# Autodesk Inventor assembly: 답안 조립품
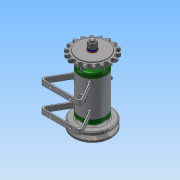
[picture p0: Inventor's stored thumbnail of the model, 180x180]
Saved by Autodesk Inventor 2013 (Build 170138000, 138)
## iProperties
Created: 2016-03
Part Number: 답안 조립품
Document SubType Name: Assembly
Designer: Administrator
Author: Administrator
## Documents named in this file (16)
- C:\Users\Administrator\Desktop\460308V1024\답안 조립품.iam
- C:\Users\Administrator\Desktop\460308V1024\본체.ipt
- C:\Users\Administrator\Desktop\460308V1024\V벨트풀리.ipt
- C:\Users\Administrator\Desktop\460308V1024\너트 M 8.ipt
- C:\Users\Administrator\Desktop\460308V1024\니플 M 6 x 0.75.ipt
- C:\Users\Administrator\Desktop\460308V1024\베어링 15 x 32 x 9.ipt
- C:\Users\Administrator\Desktop\460308V1024\볼트 M 6 x 8.ipt
- C:\Users\Administrator\Desktop\460308V1024\볼트 M4 x 12.ipt
- C:\Users\Administrator\Desktop\460308V1024\스프로킷.ipt
- C:\Users\Administrator\Desktop\460308V1024\스프링와셔 8.ipt
- C:\Users\Administrator\Desktop\460308V1024\오일 실 15 25 7.ipt
- C:\Users\Administrator\Desktop\460308V1024\와셔 6x11.5.ipt
- C:\Users\Administrator\Desktop\460308V1024\와셔 8x17.ipt
- C:\Users\Administrator\Desktop\460308V1024\축.ipt
- C:\Users\Administrator\Desktop\460308V1024\커버.ipt
- C:\Users\Administrator\Desktop\460308V1024\키 3 x 3 x 12.ipt
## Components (11 placed, 3 different names)
1. V벨트풀리:1
2. KS B 2023 6002 - 15 x 32 x 9:1
3. KS B 2023 6002 - 15 x 32 x 9:2
4. ISO 4762 M4 x 12:1
5. ISO 4762 M4 x 12:3
6. ISO 4762 M4 x 12:4
7. ISO 4762 M4 x 12:5
8. ISO 4762 M4 x 12:2
9. ISO 4762 M4 x 12:6
10. ISO 4762 M4 x 12:7
11. ISO 4762 M4 x 12:8
